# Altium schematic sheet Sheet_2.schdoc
size 314 x 216 mm
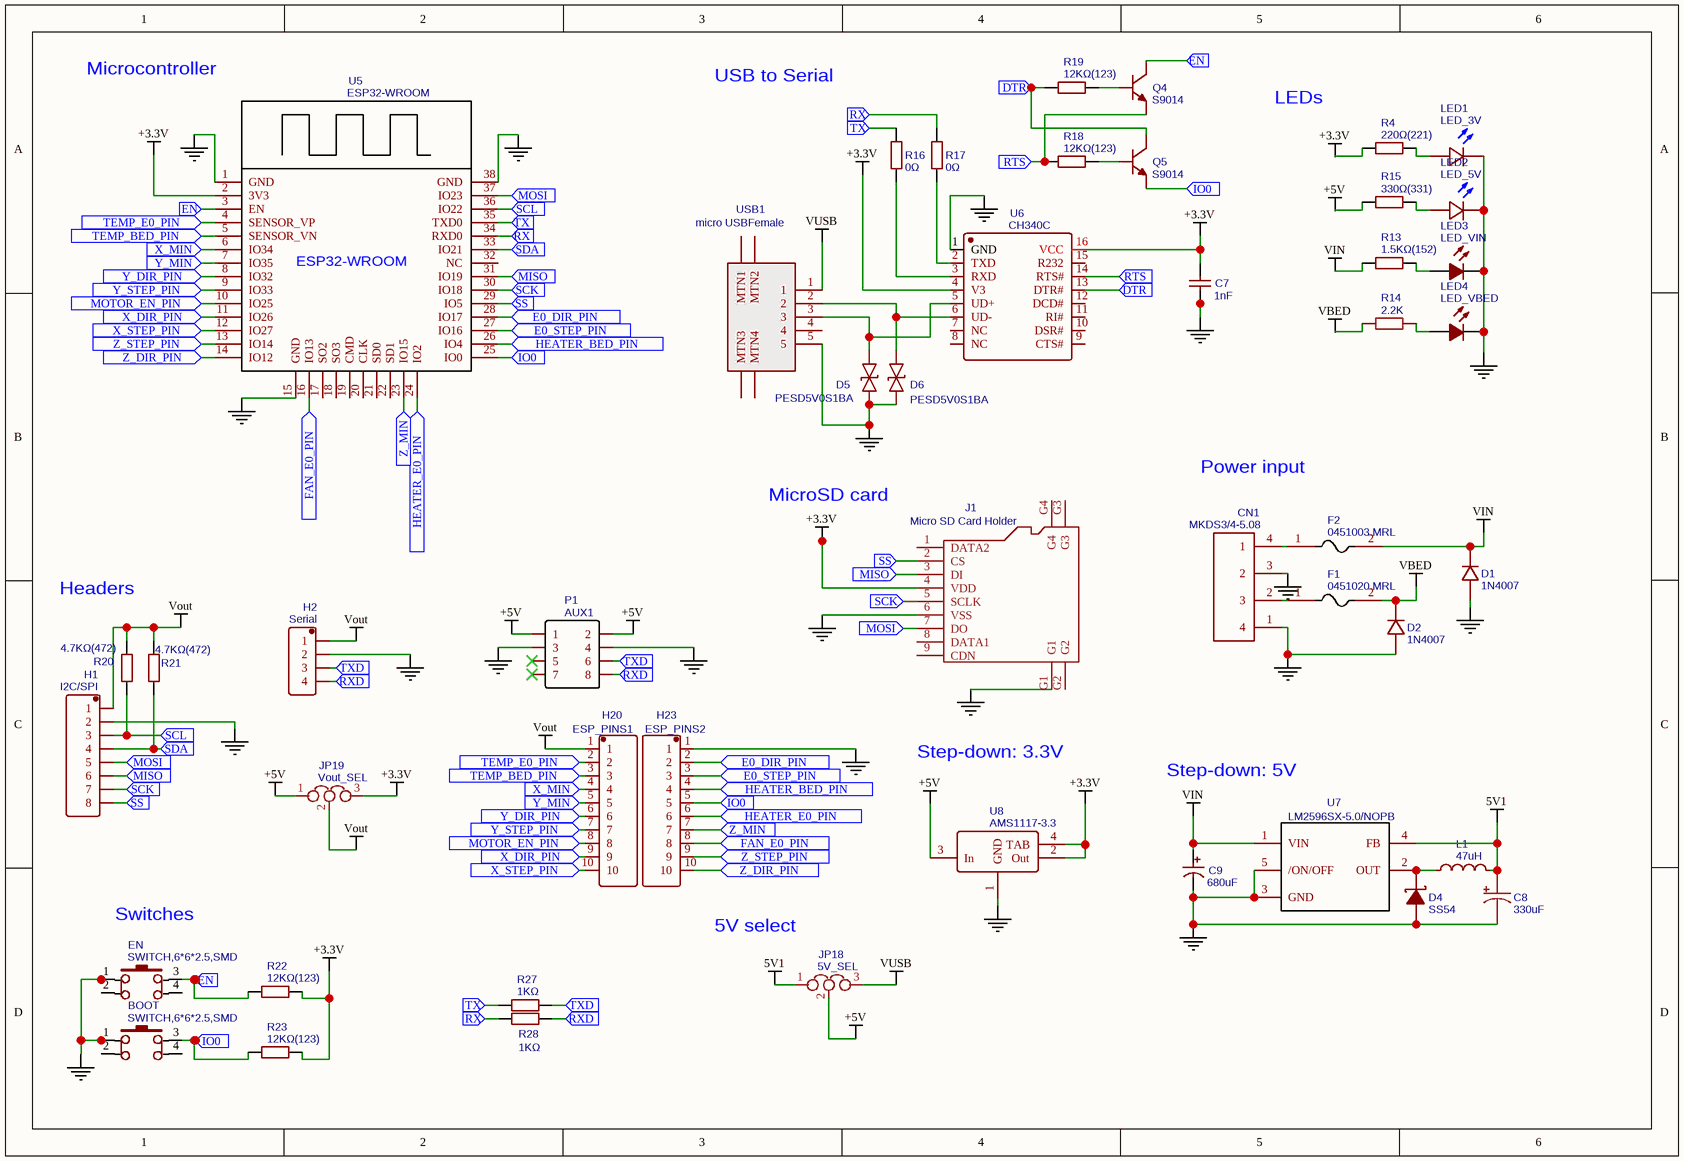
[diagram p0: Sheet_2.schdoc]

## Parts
BOOT  SWITCH,6*6*2.5,SMD  [KEY-6.0*6.0]
C7  1nF  [0805]
C8  330uF  [CAP-T-10*10]
C9  680uF  [CAP-D12.5XH13.5]
CN1  MKDS3/4-5.08  [MKDS3/4-5.08]
D1  1N4007  [SOD-123F]
D2  1N4007  [SOD-123F]
D4  SS54  [SMB(DO-214AA)]
D5  PESD5V0S1BA  [SOD-323]
D6  PESD5V0S1BA  [SOD-323]
EN  SWITCH,6*6*2.5,SMD  [KEY-6.0*6.0]
F1  0451020.MRL  [SMF_045X]
F2  0451003.MRL  [SMF_045X]
H1  I2C/SPI  [210S-1X8P]
H2  Serial  [DIP-1X4P-2.54MM-M]
H20  ESP_PINS1  [DIP-1X10P-2.54MM-M]
H23  ESP_PINS2  [DIP-1X10P-2.54MM-M]
J1  Micro SD Card Holder  [MICRO-SD9+4P-SMD-16.1X14.5X1.85MM]
JP18  5V_SEL  [HDR-3X1/2.54]
JP19  Vout_SEL  [HDR-3X1/2.54]
L1  47uH  [SLF4532]
LED1  LED_3V  [LED-0805]
LED2  LED_5V  [LED-0805]
LED3  LED_VIN  [LED-0805]
LED4  LED_VBED  [LED-0805]
P1  AUX1  [HDR-IDC-2.54-2X4P]
Q4  S9014  [SOT-23(SOT-23-3)]
Q5  S9014  [SOT-23(SOT-23-3)]
R4  220Ω(221)  [0805]
R13  1.5KΩ(152)  [0805]
R14  2.2K  [0805]
R15  330Ω(331)  [0805]
R16  0Ω  [0805]
R17  0Ω  [0805]
R18  12KΩ(123)  [0805]
R19  12KΩ(123)  [0805]
R20  4.7KΩ(472)  [0805]
R21  4.7KΩ(472)  [0805]
R22  12KΩ(123)  [0805]
R23  12KΩ(123)  [0805]
R27  1KΩ  [0805]
R28  1KΩ  [0805]
U5  ESP32-WROOM  [ESP32_WROOM_FOOTPRINT]
U6  CH340C  [SOP-16_150MIL]
U7  LM2596SX-5.0/NOPB  [TO-263-5]
U8  AMS1117-3.3  [SOT-223]
USB1  micro USBFemale  [MICRO-USB-1]

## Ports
DTR, E0_DIR_PIN, E0_STEP_PIN, EN, FAN_E0_PIN, HEATER_BED_PIN, HEATER_E0_PIN, IO0, MISO, MOSI, MOTOR_EN_PIN, RTS, RX, RXD, SCK, SCL, SDA, SS, TEMP_BED_PIN, TEMP_E0_PIN, TX, TXD, X_DIR_PIN, X_MIN, X_STEP_PIN, Y_DIR_PIN, Y_MIN, Y_STEP_PIN, Z_DIR_PIN, Z_MIN, Z_STEP_PIN

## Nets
5V1: C8.1 JP18.1 L1.2 U7.4(FB)
+3.3V: C7.1 J1.4(VDD) JP19.3 R4.1 R22.2 R23.2 U5.2(3V3) U6.4(V3) U6.16(VCC) U8.2(Out) U8.4(TAB)
+5V: JP18.2 JP19.1 P1.1 P1.2 R15.1 U8.3(In)
GND: BOOT.1 C7.2 C8.2 C9.2 CN1.1(4) CN1.3(2) D1.1(+) D2.1(+) D4.1(A) D5.2(A) D6.2(A) EN.1 H1.2 H2.2 H23.1 J1.6(VSS) J1.G1 LED1.2(-) LED2.2(-) LED3.2(C) LED4.2(C) P1.3 P1.4 U5.1(GND) U5.15(GND) U5.38(GND) U6.1(GND) U7.3(GND) U7.5(/ON/OFF) U8.1(GND) USB1.5
VBED: D2.2(-) F1.2
VIN: C9.1 D1.2(-) F2.2 R13.1 U7.1(VIN)
Vout: H1.1 H2.1 H20.1 JP19.2 R20.2 R21.2
VUSB: JP18.3 USB1.1
DTR: Q5.3(C) R19.1 U6.13(DTR#) ; port DTR
E0_DIR_PIN: H23.2 U5.28(IO17) ; port E0_DIR_PIN
E0_STEP_PIN: H23.3 U5.27(IO16) ; port E0_STEP_PIN
EN: EN.3 Q4.3(C) R22.1 U5.3(EN) ; port EN
FAN_E0_PIN: H23.8 U5.16(IO13) ; port FAN_E0_PIN
HEATER_BED_PIN: H23.4 U5.26(IO4) ; port HEATER_BED_PIN
HEATER_E0_PIN: H23.6 U5.24(IO2) ; port HEATER_E0_PIN
IO0: BOOT.3 H23.5 Q5.2(E) R23.1 U5.25(IO0) ; port IO0
MISO: H1.6 J1.3(DI) U5.31(IO19) ; port MISO
MOSI: H1.5 J1.7(DO) U5.37(IO23) ; port MOSI
MOTOR_EN_PIN: H20.8 U5.10(IO25) ; port MOTOR_EN_PIN
RTS: Q4.2(E) R18.1 U6.14(RTS#) ; port RTS
RX: R17.2 R28.1 U5.34(RXD0) ; port RX
RXD: H2.4 P1.8 R28.2 ; port RXD
SCK: H1.7 J1.5(SCLK) U5.30(IO18) ; port SCK
SCL: H1.3 R20.1 U5.36(IO22) ; port SCL
SDA: H1.4 R21.1 U5.33(IO21) ; port SDA
SS: H1.8 J1.2(CS) U5.29(IO5) ; port SS
TEMP_BED_PIN: H20.3 U5.5(SENSOR_VN) ; port TEMP_BED_PIN
TEMP_E0_PIN: H20.2 U5.4(SENSOR_VP) ; port TEMP_E0_PIN
TX: R16.2 R27.1 U5.35(TXD0) ; port TX
TXD: H2.3 P1.6 R27.2 ; port TXD
X_DIR_PIN: H20.9 U5.11(IO26) ; port X_DIR_PIN
X_MIN: H20.4 U5.6(IO34) ; port X_MIN
X_STEP_PIN: H20.10 U5.12(IO27) ; port X_STEP_PIN
Y_DIR_PIN: H20.6 U5.8(IO32) ; port Y_DIR_PIN
Y_MIN: H20.5 U5.7(IO35) ; port Y_MIN
Y_STEP_PIN: H20.7 U5.9(IO33) ; port Y_STEP_PIN
Z_DIR_PIN: H23.10 U5.14(IO12) ; port Z_DIR_PIN
Z_MIN: H23.7 U5.23(IO15) ; port Z_MIN
Z_STEP_PIN: H23.9 U5.13(IO14) ; port Z_STEP_PIN
NetCN1_2: CN1.2(3) F1.1
NetCN1_4: CN1.4(1) F2.1
NetD4_2: D4.2(K) L1.1 U7.2(OUT)
NetD5_1: D5.1(K) U6.5(UD+) USB1.3
NetD6_1: D6.1(K) U6.6(UD-) USB1.2
NetLED1_1: LED1.1(+) R4.2
NetLED2_1: LED2.1(+) R15.2
NetLED3_1: LED3.1(A) R13.2
NetQ4_1: Q4.1(B) R19.2
NetQ5_1: Q5.1(B) R18.2
NetR16_1: R16.1 U6.3(RXD)
NetR17_1: R17.1 U6.2(TXD)

Not connected (* = marked no-connect by the designer): BOOT 2 4; EN 2 4; J1 1(DATA2) 8(DATA1) 9(CDN) G2 G3 G4; LED4 1(A); P1 5* 7*; R14 1 2; U5 17(SO2) 18(SO3) 19(CMD) 20(CLK) 21(SD0) 22(SD1) 32(NC); U6 7(NC) 8(NC) 9(CTS#) 10(DSR#) 11(RI#) 12(DCD#) 15(R232); USB1 0(MTN4) 4

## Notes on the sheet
- Microcontroller
- USB to Serial
- LEDs
- MicroSD card
- Power input
- Headers
- Step-down: 3.3V
- Step-down: 5V
- (near EN) Switches
- 5V select

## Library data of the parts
BOOT EN = (no symbol name): BOM_Manufacturer: BBJ; BOM_Manufacturer Part: Switch,6*6*2.5Plastic head,260G, 0.25mm,SMD; Contributor: LCSC
C7 = (no symbol name): BOM_Manufacturer: YAGEO; BOM_Manufacturer Part: CC0805KRX7RABB102; nameAlias: Capacitance
C8 = (no symbol name): BOM_Manufacturer: LELON; BOM_Manufacturer Part: VEJ331M1VTR-1010; nameAlias: Capacitance; Contributor: LCSC
C9 = (no symbol name): BOM_Manufacturer: ROQANG; BOM_Manufacturer Part: RVT1V681M1213; nameAlias: Capacitance
CN1 = (no symbol name): BOM_Manufacturer: Phoenix Contact
D1 D2 Q4 Q5 = (no symbol name): BOM_Manufacturer: Hottech; Contributor: LCSC
D4 = (no symbol name): BOM_Manufacturer: MDD
D5 D6 = (no symbol name): BOM_Manufacturer: Nexperia; BOM_Manufacturer Part: PESD5V0S1BA,115
F1 F2 = (no symbol name): BOM_Manufacturer: Littelfuse
H1 = (no symbol name): BOM_Manufacturer: Ckmtw; BOM_Manufacturer Part: 210S-1*8P L=11.6MMGold-plated black; Contributor: LCSC
H2 = (no symbol name): BOM_Manufacturer: Ckmtw; BOM_Manufacturer Part: 210S-1*4P L=11.6MMGold-plated black; Contributor: LCSC
H20 H23 = (no symbol name): BOM_Manufacturer: Ckmtw; BOM_Manufacturer Part: 210S-1*10P L=11.6MMGold-plated black; Contributor: LCSC
J1 = (no symbol name): BOM_Manufacturer Part: LCSC; description: Micro SD Card Holder;
JP18 JP19 = (no symbol name): Contributor: KiCad
L1 = (no symbol name): BOM_Manufacturer: Sunltech; BOM_Manufacturer Part: SLF0403-470KTT; nameAlias: Value; Contributor: LCSC
LED1 LED2 = (no symbol name): BOM_Manufacturer: Everlight Elec; BOM_Manufacturer Part: 17-21/BHC-XL2M2TY/3T
LED3 LED4 = (no symbol name): BOM_Manufacturer: EVERLIGHT; BOM_Manufacturer Part: 17-21/GHC-YR1S2/3T
P1 = (no symbol name): BOM_Manufacturer: BOOMELE; BOM_Manufacturer Part: IDC Box 2X4 2.54MM
R4 = (no symbol name): BOM_Manufacturer: YAGEO; BOM_Manufacturer Part: RC0805JR-07220RL; nameAlias: Value
R13 = (no symbol name): BOM_Manufacturer: YAGEO; BOM_Manufacturer Part: RC0805JR-071K5L; nameAlias: Value
R14 = (no symbol name): BOM_Manufacturer: YAGEO; BOM_Manufacturer Part: RC0805JR-072K2L; nameAlias: Resistance (Ohms); Contributor: LCSC
R15 = (no symbol name): BOM_Manufacturer: YAGEO; BOM_Manufacturer Part: RC0805JR-07330RL; nameAlias: Value
R16 R17 = (no symbol name): BOM_Manufacturer: YAGEO; BOM_Manufacturer Part: RC0805JR-070RL; nameAlias: Value
R18 R19 R22 R23 = (no symbol name): BOM_Manufacturer: YAGEO; BOM_Manufacturer Part: RC0805JR-0712KL; nameAlias: Value
R20 R21 = (no symbol name): BOM_Manufacturer: YAGEO; BOM_Manufacturer Part: RC0805JR-074K7L; nameAlias: Value
R27 R28 = (no symbol name): BOM_Manufacturer: YAGEO; BOM_Manufacturer Part: RC0805JR-071KL; nameAlias: Value
U5 = (no symbol name): Contributor: cunt123
U6 = (no symbol name): BOM_Manufacturer: WCH
U7 = (no symbol name): BOM_Manufacturer: NS; Contributor: LCSC
U8 = (no symbol name): BOM_Manufacturer: AMS; sourceId: dwIGgezVh
USB1 = (no symbol name): BOM_Manufacturer: ValuePro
